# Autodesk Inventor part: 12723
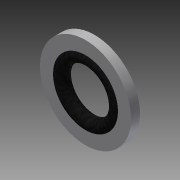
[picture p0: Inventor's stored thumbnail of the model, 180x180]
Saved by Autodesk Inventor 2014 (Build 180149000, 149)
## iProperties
Shininess: 20.0
Length Units: 11272
Angle Units: 11279
Time Units: 11290
Mass Units: 11286
Length Display Precision: 3
Angle Display Precision: 2
Company: Autodesk, Inc.
Created: 2002-07
Part Number: 12723
Material: Steel, Mild
Description: SEAL; STATO 600-0101-1/4
Document SubType Name: Modeling
Designer: Autodesk, Inc.
Density: 8.182 g/cm^3
Appearance: Steel
Density: 0.0
Volumn: 0.0
Area: 0.0
PropertySet Name: Model Information
Control State: 0
Master: False
Checked Out: False
Last Check In By: JT
Last Check In Date: 2003-06-20
Title: SEAL; STATO 600-0101-1/4
Author: Autodesk, Inc.
Comments: -
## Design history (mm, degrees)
sketch "Sketch1"
  geometry: C1 r 6.413 at (0, 0); C2 r 4.204 at (0, 0); 1 further point
  constraints: 2 centre point, 2 coincident
  dimensions: "d3" = 12.827 diameter of C1 (= OD); "d4" = 8.4074 diameter of C2 (= E_DIA - THICKNESS)
extrude "Extrusion2" new body sketch "Sketch1" stored distance "d5" = 1.27 (= THICKNESS); taper "d6" = 0 deg
sketch "Sketch2"
  geometry: L1 (0, 0)-(0, 4.018); C1 r 0.895 at (3.943, 0)
  constraints: 2 end point, 1 centre point, 1 horizontal alignment, 1 vertical
  dimensions: "d7" = 6.096 dimension on C1 L1 (= ID); "d8" = 1.7907 diameter of C1 (= -0.5 x ID + 0.5 x E_DIA)
revolve "Revolution1" sketch "Sketch2" stored, may be unused: angle "d9" = 90 deg
body "Solid1"
other parameters: "OD" = 12.827 [user parameter; used in 1 equation term], "THICKNESS" = 1.27 [user parameter; used in 2 equation terms], "E_DIA" = 9.6774 [user parameter; used in 2 equation terms], "ID" = 6.096 [user parameter; used in 2 equation terms]
